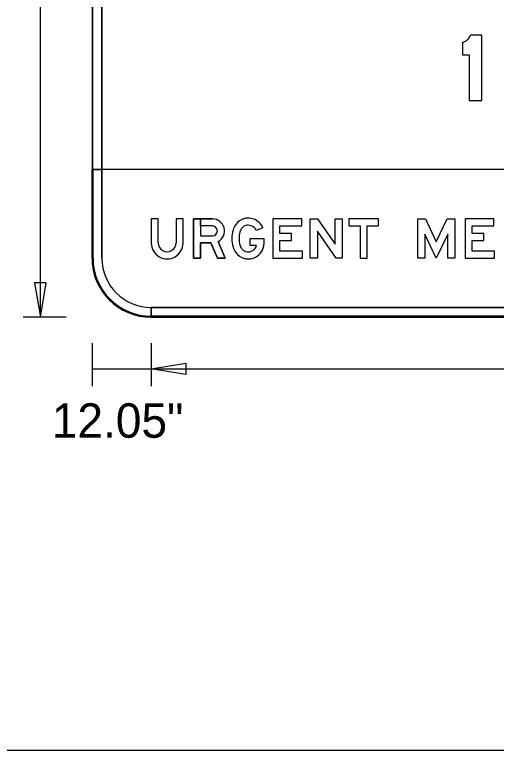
# Model space of a CAD drawing. Extents: x 17890071 to 17890754, y 17897628 to 17897992.
# Drawn here: x 17890189.47 to 17890197.63, y 17897794.28 to 17897806.75 of the extents above; entities that cross this region are included whole.
import ezdxf

# ---------------------------------------------------------------- set-up
doc = ezdxf.new("R2010")
doc.units = 0
for name, color, linetype in [('GSBWFill', 7, 'Continuous'), ('GSColorFill', 7, 'Continuous'), ('GSDims', 7, 'Continuous'), ('GSOutline', 7, 'Continuous'), ('SheetLinesMisc2_dp', 7, 'Continuous')]:
    doc.layers.add(name, color=color, linetype=linetype)

msp = doc.modelspace()

# ---------------------------------------------------------------- linework, layer by layer
at = {"layer": 'GSBWFill'}
for p, q in [((17890190.782, 17897810.621), (17890190.782, 17897802.621)), ((17890190.948, 17897802.621), (17890190.948, 17897810.621)), ((17890190.782, 17897802.621), (17890190.782, 17897804.121)), ((17890190.782, 17897804.121), (17890190.948, 17897804.121)), ((17890210.782, 17897804.121), (17890190.782, 17897804.121)), ((17890190.782, 17897804.121), (17890190.782, 17897802.621)), ((17890190.948, 17897804.121), (17890190.948, 17897803.954)), ((17890190.948, 17897803.954), (17890190.948, 17897802.621)), ((17890192.205, 17897803.288), (17890192.205, 17897802.879)), ((17890191.782, 17897801.621), (17890191.782, 17897801.788)), ((17890191.782, 17897801.788), (17890209.782, 17897801.788)), ((17890209.782, 17897801.788), (17890191.783, 17897801.788)), ((17890191.783, 17897801.788), (17890191.783, 17897801.621)), ((17890209.782, 17897801.621), (17890191.782, 17897801.621)), ((17890191.782, 17897801.621), (17890209.782, 17897801.621)), ((17890191.783, 17897801.621), (17890209.782, 17897801.621))]:
    msp.add_line(p, q, dxfattribs=at)
for points in [[(17890197.053, 17897806.277), (17890197.053, 17897806.065), (17890197.167, 17897806.065), (17890197.167, 17897805.292), (17890197.385, 17897805.292), (17890197.385, 17897806.4), (17890197.193, 17897806.4)], [(17890191.905, 17897802.879), (17890191.905, 17897803.288), (17890191.785, 17897803.288), (17890191.785, 17897802.879)], [(17890192.325, 17897802.879), (17890192.325, 17897803.288), (17890192.205, 17897803.288)], [(17890192.916, 17897802.904), (17890193.038, 17897802.621), (17890192.908, 17897802.621), (17890192.795, 17897802.881), (17890192.618, 17897802.881), (17890192.618, 17897802.621), (17890192.498, 17897802.621), (17890192.498, 17897803.288), (17890192.618, 17897803.288), (17890192.618, 17897803.001), (17890192.821, 17897803.001)], [(17890192.618, 17897803.168), (17890192.618, 17897803.288), (17890192.821, 17897803.288)], [(17890192.821, 17897803.168), (17890192.618, 17897803.168)], [(17890193.674, 17897803.136), (17890193.563, 17897803.091)], [(17890193.568, 17897802.834), (17890193.458, 17897802.834), (17890193.458, 17897802.954), (17890193.692, 17897802.954), (17890193.692, 17897802.858)]]:
    msp.add_lwpolyline(points, dxfattribs=at)
for points in [[(17890194.345, 17897802.741), (17890193.965, 17897802.741), (17890193.965, 17897802.92), (17890194.162, 17897802.92), (17890194.162, 17897803.04), (17890193.965, 17897803.04), (17890193.965, 17897803.168), (17890194.335, 17897803.168), (17890194.335, 17897803.288), (17890193.845, 17897803.288), (17890193.845, 17897802.621), (17890194.345, 17897802.621)], [(17890195.018, 17897803.288), (17890195.018, 17897802.621), (17890194.915, 17897802.621), (17890194.598, 17897803.078), (17890194.598, 17897802.621), (17890194.478, 17897802.621), (17890194.478, 17897803.288), (17890194.599, 17897803.288), (17890194.898, 17897802.856), (17890194.898, 17897803.288)], [(17890195.132, 17897803.168), (17890195.322, 17897803.168), (17890195.322, 17897802.621), (17890195.442, 17897802.621), (17890195.442, 17897803.168), (17890195.632, 17897803.168), (17890195.632, 17897803.288), (17890195.132, 17897803.288)], [(17890196.612, 17897802.9), (17890196.796, 17897803.288), (17890196.925, 17897803.288), (17890196.925, 17897802.621), (17890196.805, 17897802.621), (17890196.805, 17897803.028), (17890196.612, 17897802.621), (17890196.418, 17897803.028), (17890196.418, 17897802.621), (17890196.298, 17897802.621), (17890196.298, 17897803.288), (17890196.428, 17897803.288)], [(17890197.598, 17897802.741), (17890197.218, 17897802.741), (17890197.218, 17897802.92), (17890197.415, 17897802.92), (17890197.415, 17897803.04), (17890197.218, 17897803.04), (17890197.218, 17897803.168), (17890197.588, 17897803.168), (17890197.588, 17897803.288), (17890197.098, 17897803.288), (17890197.098, 17897802.621), (17890197.598, 17897802.621)]]:
    msp.add_lwpolyline(points, close=True, dxfattribs=at)
for centre, radius, start, end in [((17890197.007, 17897806.469), 0.198, 299.6709, 316.0835), ((17890197.007, 17897806.469), 0.198, 316.0835, 327.7887), ((17890197.007, 17897806.469), 0.198, 327.7887, 339.494), ((17890197.007, 17897806.469), 0.198, 283.2584, 299.6709), ((17890192.821, 17897803.084), 0.203, 297.837, 90), ((17890192.821, 17897803.084), 0.0833, 270, 90), ((17890191.782, 17897802.621), 1, 180, 270), ((17890191.782, 17897802.621), 1, 180, 270), ((17890191.782, 17897802.621), 1, 180, 270), ((17890191.782, 17897802.621), 0.833, 180, 270), ((17890191.782, 17897802.621), 0.833, 180, 270)]:
    msp.add_arc(centre, radius, start, end, dxfattribs=at)
for centre, major_axis, start_param, end_param in [((17890193.416, 17897803.058), (0, 0.24), 0.229188, 0.990896), ((17890193.427, 17897803.01), (0, 0.289), 0, 0.229188), ((17890193.427, 17897803.019), (0, 0.28), 5.955089, 6.283185), ((17890193.434, 17897803.039), (0, 0.259), 5.097002, 5.955089), ((17890193.656, 17897802.954), (0, 0.505), 1.282161, 1.570796), ((17890193.506, 17897802.999), (0, 0.348), 0.990896, 1.282161), ((17890193.506, 17897802.999), (0, 0.228), 0.990896, 1.282161), ((17890193.416, 17897803.058), (0, 0.12), 0.229188, 0.990896), ((17890193.427, 17897803.01), (0, 0.169), 6.283185, 6.512373), ((17890193.427, 17897803.019), (0, 0.16), 5.955089, 6.283185), ((17890193.434, 17897803.039), (0, 0.139), 5.097002, 5.955089), ((17890193.656, 17897802.954), (0, 0.505), 1.570796, 1.859431), ((17890193.656, 17897802.954), (0, 0.385), 1.282161, 1.570796), ((17890193.656, 17897802.954), (0, 0.385), 1.570796, 1.859431), ((17890192.055, 17897802.879), (0, 0.27), 1.570796, 4.712389), ((17890192.055, 17897802.879), (0, 0.15), 1.570796, 4.712389), ((17890193.506, 17897802.91), (0, 0.228), 1.859431, 2.150696), ((17890193.434, 17897802.869), (0, 0.139), 3.469689, 4.457885), ((17890193.494, 17897802.858), (0, 0.198), 4.532209, 4.712389), ((17890193.506, 17897802.91), (0, 0.348), 1.859431, 2.150696), ((17890193.416, 17897802.851), (0, 0.24), 2.150696, 2.912405), ((17890193.416, 17897802.851), (0, 0.12), 2.150696, 2.912405), ((17890193.427, 17897802.899), (0, 0.169), 2.912405, 3.141593), ((17890193.427, 17897802.889), (0, 0.16), 3.141593, 3.469689), ((17890193.434, 17897802.869), (0, 0.259), 3.469689, 4.532209), ((17890193.427, 17897802.899), (0, 0.289), 2.912405, 3.141593), ((17890193.427, 17897802.889), (0, 0.28), 3.141593, 3.469689)]:
    msp.add_ellipse(centre, major_axis=major_axis, ratio=0.999994, start_param=start_param, end_param=end_param, dxfattribs=at)
at = {"layer": 'GSColorFill'}
for p, q in [((17890190.782, 17897810.621), (17890190.782, 17897802.621)), ((17890190.782, 17897810.621), (17890190.782, 17897802.621)), ((17890190.782, 17897810.621), (17890190.782, 17897802.621)), ((17890190.798, 17897802.621), (17890190.798, 17897810.621)), ((17890190.948, 17897802.621), (17890190.948, 17897810.621)), ((17890210.782, 17897804.121), (17890190.782, 17897804.121)), ((17890190.782, 17897804.121), (17890190.782, 17897802.621)), ((17890190.782, 17897802.621), (17890190.782, 17897804.121)), ((17890190.782, 17897804.121), (17890190.948, 17897804.121)), ((17890190.782, 17897802.621), (17890190.782, 17897804.121)), ((17890190.782, 17897804.121), (17890190.798, 17897804.121)), ((17890190.798, 17897804.121), (17890190.798, 17897804.104)), ((17890190.798, 17897804.104), (17890190.798, 17897802.621)), ((17890190.948, 17897804.121), (17890190.948, 17897803.954)), ((17890190.948, 17897803.954), (17890190.948, 17897802.621)), ((17890192.205, 17897803.288), (17890192.205, 17897802.879)), ((17890191.782, 17897801.621), (17890191.782, 17897801.788)), ((17890191.782, 17897801.788), (17890209.782, 17897801.788)), ((17890209.782, 17897801.788), (17890191.783, 17897801.788)), ((17890191.783, 17897801.788), (17890191.783, 17897801.621)), ((17890191.782, 17897801.621), (17890191.782, 17897801.638)), ((17890209.782, 17897801.638), (17890191.782, 17897801.638)), ((17890191.782, 17897801.638), (17890191.782, 17897801.621)), ((17890191.782, 17897801.638), (17890209.782, 17897801.638)), ((17890191.782, 17897801.621), (17890209.782, 17897801.621)), ((17890191.782, 17897801.621), (17890209.782, 17897801.621)), ((17890191.782, 17897801.621), (17890209.782, 17897801.621)), ((17890209.782, 17897801.621), (17890191.782, 17897801.621)), ((17890209.782, 17897801.621), (17890191.782, 17897801.621)), ((17890191.783, 17897801.621), (17890209.782, 17897801.621))]:
    msp.add_line(p, q, dxfattribs=at)
for points in [[(17890197.053, 17897806.277), (17890197.053, 17897806.065), (17890197.167, 17897806.065), (17890197.167, 17897805.292), (17890197.385, 17897805.292), (17890197.385, 17897806.4), (17890197.193, 17897806.4)], [(17890191.905, 17897802.879), (17890191.905, 17897803.288), (17890191.785, 17897803.288), (17890191.785, 17897802.879)], [(17890192.325, 17897802.879), (17890192.325, 17897803.288), (17890192.205, 17897803.288)], [(17890192.916, 17897802.904), (17890193.038, 17897802.621), (17890192.908, 17897802.621), (17890192.795, 17897802.881), (17890192.618, 17897802.881), (17890192.618, 17897802.621), (17890192.498, 17897802.621), (17890192.498, 17897803.288), (17890192.618, 17897803.288), (17890192.618, 17897803.001), (17890192.821, 17897803.001)], [(17890192.618, 17897803.168), (17890192.618, 17897803.288), (17890192.821, 17897803.288)], [(17890192.821, 17897803.168), (17890192.618, 17897803.168)], [(17890193.674, 17897803.136), (17890193.563, 17897803.091)], [(17890193.568, 17897802.834), (17890193.458, 17897802.834), (17890193.458, 17897802.954), (17890193.692, 17897802.954), (17890193.692, 17897802.858)]]:
    msp.add_lwpolyline(points, dxfattribs=at)
for points in [[(17890194.345, 17897802.741), (17890193.965, 17897802.741), (17890193.965, 17897802.92), (17890194.162, 17897802.92), (17890194.162, 17897803.04), (17890193.965, 17897803.04), (17890193.965, 17897803.168), (17890194.335, 17897803.168), (17890194.335, 17897803.288), (17890193.845, 17897803.288), (17890193.845, 17897802.621), (17890194.345, 17897802.621)], [(17890195.018, 17897803.288), (17890195.018, 17897802.621), (17890194.915, 17897802.621), (17890194.598, 17897803.078), (17890194.598, 17897802.621), (17890194.478, 17897802.621), (17890194.478, 17897803.288), (17890194.599, 17897803.288), (17890194.898, 17897802.856), (17890194.898, 17897803.288)], [(17890195.132, 17897803.168), (17890195.322, 17897803.168), (17890195.322, 17897802.621), (17890195.442, 17897802.621), (17890195.442, 17897803.168), (17890195.632, 17897803.168), (17890195.632, 17897803.288), (17890195.132, 17897803.288)], [(17890196.612, 17897802.9), (17890196.796, 17897803.288), (17890196.925, 17897803.288), (17890196.925, 17897802.621), (17890196.805, 17897802.621), (17890196.805, 17897803.028), (17890196.612, 17897802.621), (17890196.418, 17897803.028), (17890196.418, 17897802.621), (17890196.298, 17897802.621), (17890196.298, 17897803.288), (17890196.428, 17897803.288)], [(17890197.598, 17897802.741), (17890197.218, 17897802.741), (17890197.218, 17897802.92), (17890197.415, 17897802.92), (17890197.415, 17897803.04), (17890197.218, 17897803.04), (17890197.218, 17897803.168), (17890197.588, 17897803.168), (17890197.588, 17897803.288), (17890197.098, 17897803.288), (17890197.098, 17897802.621), (17890197.598, 17897802.621)]]:
    msp.add_lwpolyline(points, close=True, dxfattribs=at)
for centre, radius, start, end in [((17890197.007, 17897806.469), 0.198, 299.6709, 316.0835), ((17890197.007, 17897806.469), 0.198, 316.0835, 327.7887), ((17890197.007, 17897806.469), 0.198, 327.7887, 339.494), ((17890197.007, 17897806.469), 0.198, 283.2584, 299.6709), ((17890192.821, 17897803.084), 0.203, 297.837, 90), ((17890192.821, 17897803.084), 0.0833, 270, 90), ((17890191.782, 17897802.621), 1, 180, 270), ((17890191.782, 17897802.621), 1, 180, 270), ((17890191.782, 17897802.621), 1, 180, 270), ((17890191.782, 17897802.621), 1, 180, 270), ((17890191.782, 17897802.621), 1, 180, 270), ((17890191.782, 17897802.621), 1, 180, 270), ((17890191.782, 17897802.621), 0.983, 180, 270), ((17890191.782, 17897802.621), 0.983, 180, 270), ((17890191.782, 17897802.621), 0.833, 180, 270), ((17890191.782, 17897802.621), 0.833, 180, 270)]:
    msp.add_arc(centre, radius, start, end, dxfattribs=at)
for centre, major_axis, start_param, end_param in [((17890193.416, 17897803.058), (0, 0.24), 0.229188, 0.990896), ((17890193.427, 17897803.01), (0, 0.289), 0, 0.229188), ((17890193.427, 17897803.019), (0, 0.28), 5.955089, 6.283185), ((17890193.434, 17897803.039), (0, 0.259), 5.097002, 5.955089), ((17890193.656, 17897802.954), (0, 0.505), 1.282161, 1.570796), ((17890193.506, 17897802.999), (0, 0.348), 0.990896, 1.282161), ((17890193.506, 17897802.999), (0, 0.228), 0.990896, 1.282161), ((17890193.416, 17897803.058), (0, 0.12), 0.229188, 0.990896), ((17890193.427, 17897803.01), (0, 0.169), 6.283185, 6.512373), ((17890193.427, 17897803.019), (0, 0.16), 5.955089, 6.283185), ((17890193.434, 17897803.039), (0, 0.139), 5.097002, 5.955089), ((17890193.656, 17897802.954), (0, 0.505), 1.570796, 1.859431), ((17890193.656, 17897802.954), (0, 0.385), 1.282161, 1.570796), ((17890193.656, 17897802.954), (0, 0.385), 1.570796, 1.859431), ((17890192.055, 17897802.879), (0, 0.27), 1.570796, 4.712389), ((17890192.055, 17897802.879), (0, 0.15), 1.570796, 4.712389), ((17890193.506, 17897802.91), (0, 0.228), 1.859431, 2.150696), ((17890193.434, 17897802.869), (0, 0.139), 3.469689, 4.457885), ((17890193.494, 17897802.858), (0, 0.198), 4.532209, 4.712389), ((17890193.506, 17897802.91), (0, 0.348), 1.859431, 2.150696), ((17890193.416, 17897802.851), (0, 0.24), 2.150696, 2.912405), ((17890193.416, 17897802.851), (0, 0.12), 2.150696, 2.912405), ((17890193.427, 17897802.899), (0, 0.169), 2.912405, 3.141593), ((17890193.427, 17897802.889), (0, 0.16), 3.141593, 3.469689), ((17890193.434, 17897802.869), (0, 0.259), 3.469689, 4.532209), ((17890193.427, 17897802.899), (0, 0.289), 2.912405, 3.141593), ((17890193.427, 17897802.889), (0, 0.28), 3.141593, 3.469689)]:
    msp.add_ellipse(centre, major_axis=major_axis, ratio=0.999994, start_param=start_param, end_param=end_param, dxfattribs=at)
at = {"layer": 'GSDims'}
for p, q in [((17890189.907, 17897801.621), (17890189.907, 17897811.621)), ((17890190.344, 17897801.621), (17890189.615, 17897801.621)), ((17890190.782, 17897801.183), (17890190.782, 17897800.454)), ((17890191.785, 17897801.183), (17890191.785, 17897800.454)), ((17890191.785, 17897801.183), (17890191.785, 17897800.454)), ((17890190.782, 17897800.746), (17890191.785, 17897800.746)), ((17890191.785, 17897800.746), (17890209.778, 17897800.746))]:
    msp.add_line(p, q, dxfattribs=at)
for points in [[(17890189.907, 17897801.621), (17890190.004, 17897802.204), (17890189.809, 17897802.204)], [(17890191.785, 17897800.746), (17890192.368, 17897800.843), (17890192.368, 17897800.649)]]:
    msp.add_lwpolyline(points, close=True, dxfattribs=at)
at = {"layer": 'GSOutline'}
for p, q in [((17890190.782, 17897810.621), (17890190.782, 17897802.621)), ((17890190.948, 17897810.621), (17890190.948, 17897802.621)), ((17890190.782, 17897802.621), (17890190.782, 17897804.121)), ((17890190.782, 17897804.121), (17890190.948, 17897804.121)), ((17890210.782, 17897804.121), (17890190.782, 17897804.121)), ((17890190.782, 17897804.121), (17890190.782, 17897802.621)), ((17890190.948, 17897804.121), (17890190.948, 17897803.954)), ((17890190.948, 17897803.954), (17890190.948, 17897802.621)), ((17890192.205, 17897803.288), (17890192.205, 17897802.879)), ((17890191.782, 17897801.788), (17890209.782, 17897801.788)), ((17890191.782, 17897801.788), (17890209.782, 17897801.788)), ((17890191.782, 17897801.621), (17890209.782, 17897801.621)), ((17890209.782, 17897801.621), (17890191.782, 17897801.621)), ((17890191.782, 17897801.621), (17890209.782, 17897801.621))]:
    msp.add_line(p, q, dxfattribs=at)
for points in [[(17890197.053, 17897806.277), (17890197.053, 17897806.065), (17890197.167, 17897806.065), (17890197.167, 17897805.292), (17890197.385, 17897805.292), (17890197.385, 17897806.4), (17890197.193, 17897806.4)], [(17890191.905, 17897802.879), (17890191.905, 17897803.288), (17890191.785, 17897803.288), (17890191.785, 17897802.879)], [(17890192.325, 17897802.879), (17890192.325, 17897803.288), (17890192.205, 17897803.288)], [(17890192.821, 17897803.288), (17890192.498, 17897803.288), (17890192.498, 17897802.621), (17890192.618, 17897802.621), (17890192.618, 17897802.881), (17890192.795, 17897802.881), (17890192.908, 17897802.621), (17890193.038, 17897802.621), (17890192.916, 17897802.904)], [(17890192.821, 17897803.168), (17890192.618, 17897803.168), (17890192.618, 17897803.001), (17890192.821, 17897803.001)], [(17890193.674, 17897803.136), (17890193.563, 17897803.091)], [(17890193.568, 17897802.834), (17890193.458, 17897802.834), (17890193.458, 17897802.954), (17890193.692, 17897802.954), (17890193.692, 17897802.858)]]:
    msp.add_lwpolyline(points, dxfattribs=at)
for points in [[(17890194.345, 17897802.741), (17890193.965, 17897802.741), (17890193.965, 17897802.92), (17890194.162, 17897802.92), (17890194.162, 17897803.04), (17890193.965, 17897803.04), (17890193.965, 17897803.168), (17890194.335, 17897803.168), (17890194.335, 17897803.288), (17890193.845, 17897803.288), (17890193.845, 17897802.621), (17890194.345, 17897802.621)], [(17890195.018, 17897803.288), (17890195.018, 17897802.621), (17890194.915, 17897802.621), (17890194.598, 17897803.078), (17890194.598, 17897802.621), (17890194.478, 17897802.621), (17890194.478, 17897803.288), (17890194.599, 17897803.288), (17890194.898, 17897802.856), (17890194.898, 17897803.288)], [(17890195.132, 17897803.168), (17890195.322, 17897803.168), (17890195.322, 17897802.621), (17890195.442, 17897802.621), (17890195.442, 17897803.168), (17890195.632, 17897803.168), (17890195.632, 17897803.288), (17890195.132, 17897803.288)], [(17890196.612, 17897802.9), (17890196.796, 17897803.288), (17890196.925, 17897803.288), (17890196.925, 17897802.621), (17890196.805, 17897802.621), (17890196.805, 17897803.028), (17890196.612, 17897802.621), (17890196.418, 17897803.028), (17890196.418, 17897802.621), (17890196.298, 17897802.621), (17890196.298, 17897803.288), (17890196.428, 17897803.288)], [(17890197.598, 17897802.741), (17890197.218, 17897802.741), (17890197.218, 17897802.92), (17890197.415, 17897802.92), (17890197.415, 17897803.04), (17890197.218, 17897803.04), (17890197.218, 17897803.168), (17890197.588, 17897803.168), (17890197.588, 17897803.288), (17890197.098, 17897803.288), (17890197.098, 17897802.621), (17890197.598, 17897802.621)]]:
    msp.add_lwpolyline(points, close=True, dxfattribs=at)
for centre, radius, start, end in [((17890197.007, 17897806.469), 0.198, 299.6709, 316.0835), ((17890197.007, 17897806.469), 0.198, 316.0835, 327.7887), ((17890197.007, 17897806.469), 0.198, 327.7887, 339.494), ((17890197.007, 17897806.469), 0.198, 283.2584, 299.6709), ((17890192.821, 17897803.084), 0.203, 297.837, 90), ((17890192.821, 17897803.084), 0.0833, 270, 90), ((17890191.782, 17897802.621), 1, 180, 270), ((17890191.782, 17897802.621), 1, 180, 270), ((17890191.782, 17897802.621), 1, 180, 270), ((17890191.782, 17897802.621), 0.833, 180, 270), ((17890191.782, 17897802.621), 0.833, 180, 270)]:
    msp.add_arc(centre, radius, start, end, dxfattribs=at)
for centre, major_axis, start_param, end_param in [((17890193.416, 17897803.058), (0, 0.24), 0.229188, 0.990896), ((17890193.427, 17897803.01), (0, 0.289), 0, 0.229188), ((17890193.427, 17897803.019), (0, 0.28), 5.955089, 6.283185), ((17890193.434, 17897803.039), (0, 0.259), 5.097002, 5.955089), ((17890193.656, 17897802.954), (0, 0.505), 1.282161, 1.570796), ((17890193.506, 17897802.999), (0, 0.348), 0.990896, 1.282161), ((17890193.506, 17897802.999), (0, 0.228), 0.990896, 1.282161), ((17890193.416, 17897803.058), (0, 0.12), 0.229188, 0.990896), ((17890193.427, 17897803.01), (0, 0.169), 6.283185, 6.512373), ((17890193.427, 17897803.019), (0, 0.16), 5.955089, 6.283185), ((17890193.434, 17897803.039), (0, 0.139), 5.097002, 5.955089), ((17890193.656, 17897802.954), (0, 0.505), 1.570796, 1.859431), ((17890193.656, 17897802.954), (0, 0.385), 1.282161, 1.570796), ((17890193.656, 17897802.954), (0, 0.385), 1.570796, 1.859431), ((17890192.055, 17897802.879), (0, 0.27), 1.570796, 4.712389), ((17890192.055, 17897802.879), (0, 0.15), 1.570796, 4.712389), ((17890193.506, 17897802.91), (0, 0.228), 1.859431, 2.150696), ((17890193.434, 17897802.869), (0, 0.139), 3.469689, 4.457885), ((17890193.494, 17897802.858), (0, 0.198), 4.532209, 4.712389), ((17890193.506, 17897802.91), (0, 0.348), 1.859431, 2.150696), ((17890193.416, 17897802.851), (0, 0.24), 2.150696, 2.912405), ((17890193.416, 17897802.851), (0, 0.12), 2.150696, 2.912405), ((17890193.427, 17897802.899), (0, 0.169), 2.912405, 3.141593), ((17890193.427, 17897802.889), (0, 0.16), 3.141593, 3.469689), ((17890193.434, 17897802.869), (0, 0.259), 3.469689, 4.532209), ((17890193.427, 17897802.899), (0, 0.289), 2.912405, 3.141593), ((17890193.427, 17897802.889), (0, 0.28), 3.141593, 3.469689)]:
    msp.add_ellipse(centre, major_axis=major_axis, ratio=0.999994, start_param=start_param, end_param=end_param, dxfattribs=at)
at = {"layer": 'SheetLinesMisc2_dp'}
msp.add_line((17890175.209, 17897794.284), (17890226.38, 17897794.284), dxfattribs=at)

# ---------------------------------------------------------------- texts
at = {"layer": 'GSDims'}
msp.add_text('12.05"', height=0.5833, dxfattribs=at).set_placement((17890190.101, 17897799.579))

doc.saveas('drawing.dxf')
